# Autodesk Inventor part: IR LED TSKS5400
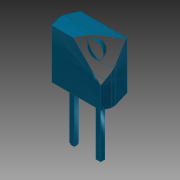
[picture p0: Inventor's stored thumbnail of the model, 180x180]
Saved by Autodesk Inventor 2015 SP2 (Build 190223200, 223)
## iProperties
Created: 2012-08
Part Number: IR LED TSKS5400
Material: PC/ABS-Kunststoff
Document SubType Name: Modeling
Designer: rYan
Mass: 0.0905656 g
Surface Area: 1.15542 cm^2
Volume: 0.0606601 cm^3
Density: 1.493 g/cm^3
Appearance: Himmelblau- dunkel
Author: rYan
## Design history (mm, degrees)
sketch "Skizze2"
  geometry: L1 (-2.253, 1.325)-(2.253, 1.325); L2 (2.5, -0.075)-(2.5, -0.475); L3 (2.35, -1.325)-(-2.35, -1.325); L4 (-2.5, -0.475)-(-2.5, -0.075); L5 (-3.5, 0)-(3.5, 0) reference; L6 (0, 1.855)-(0, -1.855) reference; L7 (2.253, 1.325)-(2.5, -0.075); L8 (2.5, -0.475)-(2.35, -1.325); L9 (-2.253, 1.325)-(-2.5, -0.075); L10 (-2.5, -0.475)-(-2.35, -1.325); 1 further point
  constraints: 16 end point, 2 parallel, 1 horizontal, 1 perpendicular, 4 other
  dimensions: "d5" = 2.65 distance between parallel lines of L3 L1; "d7" = 5 distance between parallel lines of L2 L4; "d8" = 1.4 distance from line of L2.start L1; "d9" = 10 deg angle of L7 L2; "d11" = 10 deg angle of L8 L2; "d12" = 0.4 distance of L2.start L2.end
extrude "Extrusion1" new body sketch "Skizze2" distance "d3" = 5; taper "d4" = 0 deg
sketch "Skizze3"
  geometry: L1 (4.506, -5)-(0, -5) reference; L2 (2.253, -5)-(2.253, 0); L3 (4.506, 0)-(0, 0) reference; C1 r 1.6 at (2.253, -3.1)
  constraints: 2 end point, 1 centre point, 1 midpoint, 1 perpendicular, 1 point on line
  dimensions: "d13" = 3.2 diameter of C1; "d21" = 3.1 distance from line of C1.centre L3
extrude "Extrusion2" cut sketch "Skizze3" distance "d15" = 0.8; taper "d16" = -45 deg
sketch "Skizze4"
  geometry: L1 (0, 0.75)-(0, -0.75); C1 r 0.8 at (0, 0) reference; A1 r 0.75 centre (0, 0) between (0, 0.75) and (0, -0.75); 2 further points
  constraints: 2 coincident, 2 end point, 2 point on circle, 1 centre point, 1 midpoint, 1 vertical
  dimensions: "d17" = 1.5 diameter of A1
revolve "Umdrehung1" sketch "Skizze4" stored, may be unused: angle "d18" = 90 deg
chamfer "Fase1" distance "d22" = 1.4; stored, may be unused: second distance "d23" = 2, angle "d24" = 10 deg
chamfer "Fase2" distance "d25" = 1.4; stored, may be unused: second distance "d26" = 2, angle "d27" = 10 deg
chamfer "Fase3" distance "d28" = 0.8; stored, may be unused: second distance "d29" = 2, angle "d30" = 10 deg
chamfer "Fase4" distance "d31" = 0.8; stored, may be unused: second distance "d32" = 2, angle "d33" = 10 deg
sketch "Skizze5"
  geometry: L1 (-2.5, -0.075)-(2.5, -0.075) reference; L2 (0, -1.855)-(0, 1.855) reference; L3 (-1.495, -0.075)-(-1.045, -0.075); L4 (-1.045, -0.075)-(-1.045, -0.475); L5 (-1.045, -0.475)-(-1.495, -0.475); L6 (-1.495, -0.475)-(-1.495, -0.075); L7 (1.045, -0.075)-(1.495, -0.075); L8 (1.495, -0.075)-(1.495, -0.475); L9 (1.495, -0.475)-(1.045, -0.475); L10 (1.045, -0.475)-(1.045, -0.075); 1 further point
  constraints: 16 end point, 4 parallel, 2 horizontal, 2 perpendicular, 1 collinear, 4 other
  dimensions: "d34" = 0.45 distance of L3.start L3.end; "d36" = 0.4 distance of L3.end L4.end; "d37" = 2.09 distance between parallel lines of L10 L4
extrude "Extrusion3" join sketch "Skizze5" distance "d38" = 5; taper "d39" = 0 deg
node "Volumenkörper1"
